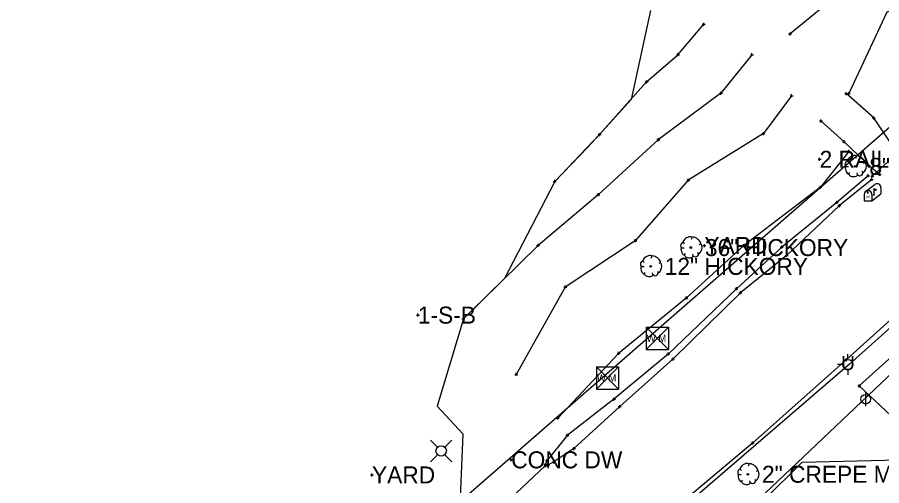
# Model space of a CAD drawing. Extents: x -1 to 1157254, y -1 to 2021979.
# Drawn here: x 1147084.1 to 1147450.2, y 2017275.4 to 2017473.9 of the extents above; entities that cross this region are included whole.
import ezdxf

# ---------------------------------------------------------------- set-up
doc = ezdxf.new("R2010")
doc.units = 0
for name, color, linetype in [('S_BUILDING_ANNOT', 7, 'Continuous'), ('S_CAL_CORNER_ANNOT', 7, 'Continuous'), ('S_CATCH_BASIN', 7, 'Continuous'), ('S_CONTOUR_ANNOT', 7, 'Continuous'), ('S_CONTOUR_MAJOR', 7, 'Continuous'), ('S_CROSS_DRAIN', 7, 'Continuous'), ('S_CTL_TABLE', 7, 'Continuous'), ('S_CURB', 7, 'Continuous'), ('S_DRIVEWAY_ANNOT', 7, 'Continuous'), ('S_DROP_INLET', 7, 'Continuous'), ('S_DROP_INLET_ANNOT', 7, 'Continuous'), ('S_EDGE_BITUMINOUS_ANNOT', 7, 'Continuous'), ('S_ENV_CONSTRAINT', 7, 'Continuous'), ('S_FENCE', 7, 'Continuous'), ('S_GAS_PUMP_ISLAND_ANNOT', 7, 'Continuous'), ('S_GATE', 7, 'Continuous'), ('S_GATE_ANNOT', 7, 'Continuous')]:
    doc.layers.add(name, color=color, linetype=linetype)

msp = doc.modelspace()

# ---------------------------------------------------------------- linework, layer by layer
at = {"layer": 'S_BUILDING_ANNOT'}
for p, q in [((1147435.23, 2017440.88), (1147435.23, 2017442.16)), ((1147434.6, 2017441.52), (1147435.87, 2017441.52)), ((1147435.23, 2017441.52), (1147435.23, 2017441.52)), ((1147446.26, 2017431.23), (1147447.53, 2017431.23)), ((1147446.89, 2017430.59), (1147446.89, 2017431.87)), ((1147446.89, 2017431.23), (1147446.89, 2017431.23)), ((1147423.84, 2017429.96), (1147425.11, 2017429.96)), ((1147424.48, 2017429.32), (1147424.48, 2017430.59)), ((1147424.48, 2017429.96), (1147424.48, 2017429.96)), ((1147433.64, 2017421.15), (1147434.91, 2017421.15)), ((1147434.28, 2017420.52), (1147434.28, 2017421.79)), ((1147434.28, 2017421.15), (1147434.28, 2017421.15)), ((1147423.31, 2017413.68), (1147424.58, 2017413.68)), ((1147423.94, 2017413.04), (1147423.94, 2017414.31)), ((1147423.94, 2017413.68), (1147423.94, 2017413.68)), ((1147443.32, 2017411.89), (1147443.31, 2017413.16)), ((1147442.68, 2017412.53), (1147443.95, 2017412.53)), ((1147443.31, 2017412.53), (1147443.31, 2017412.53)), ((1147443.85, 2017406.72), (1147445.12, 2017406.72)), ((1147444.49, 2017406.09), (1147444.49, 2017407.36)), ((1147444.49, 2017406.72), (1147444.49, 2017406.72)), ((1147445.58, 2017406.59), (1147446.86, 2017406.59)), ((1147446.02, 2017404.54), (1147446.01, 2017405.82)), ((1147446.22, 2017405.96), (1147446.22, 2017407.23)), ((1147446.22, 2017406.59), (1147446.22, 2017406.59)), ((1147448.78, 2017407.27), (1147450.06, 2017407.27)), ((1147449.42, 2017406.64), (1147449.42, 2017407.91)), ((1147449.42, 2017407.27), (1147449.42, 2017407.27)), ((1147445.38, 2017405.18), (1147446.65, 2017405.18)), ((1147446.01, 2017405.18), (1147446.01, 2017405.18)), ((1147430.58, 2017395.42), (1147431.85, 2017395.42)), ((1147431.22, 2017394.78), (1147431.22, 2017396.05)), ((1147431.22, 2017395.42), (1147431.22, 2017395.42)), ((1147432.34, 2017393.43), (1147432.34, 2017394.7)), ((1147431.7, 2017394.06), (1147432.98, 2017394.06)), ((1147432.34, 2017394.06), (1147432.34, 2017394.06)), ((1147374.5, 2017377.15), (1147375.77, 2017377.15)), ((1147375.13, 2017376.51), (1147375.13, 2017377.79)), ((1147375.13, 2017377.15), (1147375.13, 2017377.15)), ((1147407.28, 2017376.47), (1147408.56, 2017376.48)), ((1147407.92, 2017375.84), (1147407.92, 2017377.11)), ((1147407.92, 2017376.48), (1147407.92, 2017376.48)), ((1147409.34, 2017372.95), (1147410.61, 2017372.96)), ((1147409.97, 2017372.32), (1147409.97, 2017373.59)), ((1147409.97, 2017372.96), (1147409.97, 2017372.96)), ((1147388.04, 2017358.85), (1147389.31, 2017358.85)), ((1147388.68, 2017358.22), (1147388.67, 2017359.49)), ((1147388.68, 2017358.85), (1147388.68, 2017358.85)), ((1147390.38, 2017356.48), (1147390.38, 2017357.75)), ((1147389.74, 2017357.12), (1147391.02, 2017357.12)), ((1147390.38, 2017357.12), (1147390.38, 2017357.12)), ((1147253.16, 2017347.66), (1147254.43, 2017347.66)), ((1147253.8, 2017347.03), (1147253.79, 2017348.3)), ((1147253.79, 2017347.66), (1147253.79, 2017347.66)), ((1147359.14, 2017331.13), (1147360.41, 2017331.14)), ((1147359.78, 2017330.5), (1147359.78, 2017331.77)), ((1147359.78, 2017331.13), (1147359.78, 2017331.13)), ((1147361.23, 2017329.08), (1147362.51, 2017329.08)), ((1147361.87, 2017328.45), (1147361.87, 2017329.72)), ((1147361.87, 2017329.08), (1147361.87, 2017329.08)), ((1147434.65, 2017328.79), (1147435.92, 2017328.8)), ((1147435.29, 2017328.16), (1147435.28, 2017329.43)), ((1147435.29, 2017328.79), (1147435.29, 2017328.79)), ((1147336.21, 2017312.03), (1147337.48, 2017312.03)), ((1147336.84, 2017311.4), (1147336.84, 2017312.67)), ((1147336.84, 2017312.03), (1147336.84, 2017312.03)), ((1147338.65, 2017308.93), (1147339.92, 2017308.93)), ((1147339.29, 2017308.29), (1147339.28, 2017309.56)), ((1147339.28, 2017308.93), (1147339.28, 2017308.93)), ((1147316.4, 2017296.71), (1147317.68, 2017296.71)), ((1147317.04, 2017296.08), (1147317.04, 2017297.35)), ((1147317.04, 2017296.71), (1147317.04, 2017296.71)), ((1147394.89, 2017293.45), (1147396.16, 2017293.46)), ((1147395.53, 2017292.82), (1147395.53, 2017294.09)), ((1147395.53, 2017293.46), (1147395.53, 2017293.46)), ((1147319.27, 2017291.08), (1147320.54, 2017291.08)), ((1147319.91, 2017290.45), (1147319.9, 2017291.72)), ((1147319.91, 2017291.08), (1147319.91, 2017291.08)), ((1147292.68, 2017286.34), (1147293.95, 2017286.34)), ((1147293.32, 2017285.71), (1147293.32, 2017286.98)), ((1147293.32, 2017286.34), (1147293.32, 2017286.34)), ((1147307.78, 2017283.2), (1147307.77, 2017284.47)), ((1147307.82, 2017285.94), (1147309.09, 2017285.94)), ((1147307.84, 2017283.72), (1147307.84, 2017284.99)), ((1147308.46, 2017285.31), (1147308.46, 2017286.58)), ((1147308.46, 2017285.94), (1147308.46, 2017285.94)), ((1147308.89, 2017283.46), (1147308.89, 2017284.73)), ((1147310.74, 2017285.47), (1147312.01, 2017285.47)), ((1147311.38, 2017284.84), (1147311.38, 2017286.11)), ((1147311.38, 2017285.47), (1147311.38, 2017285.47)), ((1147307.14, 2017283.83), (1147308.41, 2017283.84)), ((1147307.2, 2017284.35), (1147308.47, 2017284.36)), ((1147307.77, 2017283.83), (1147307.77, 2017283.83)), ((1147307.84, 2017284.36), (1147307.84, 2017284.36)), ((1147308.26, 2017284.09), (1147309.53, 2017284.1)), ((1147308.89, 2017284.09), (1147308.89, 2017284.09)), ((1147233.73, 2017279.96), (1147235, 2017279.96)), ((1147234.36, 2017279.32), (1147234.36, 2017280.59)), ((1147234.36, 2017279.96), (1147234.36, 2017279.96))]:
    msp.add_line(p, q, dxfattribs=at)
at = {"layer": 'S_CAL_CORNER_ANNOT'}
msp.add_lwpolyline([(1148176.11, 2017926.04), (1148136.14, 2017895.28), (1148103.22, 2017868.95), (1148054.86, 2017832.59), (1147994.13, 2017784.96), (1147955.31, 2017755.81), (1147823.06, 2017654.27), (1147729.59, 2017581.35), (1147643.02, 2017515.61), (1147594.54, 2017475.05), (1147501.21, 2017388.35), (1147435.29, 2017328.79), (1147395.53, 2017293.46), (1147348.75, 2017254.13), (1147258.66, 2017171.57), (1147166.99, 2017089.79), (1147151.24, 2017076.13), (1147027.41, 2016982.56), (1146975.56, 2016939.41), (1146851.18, 2016835.15), (1146821.23, 2016867.05), (1146788.36, 2016903.2)], dxfattribs=at)
at = {"layer": 'S_CATCH_BASIN'}
for p, q in [((1147435.92, 2017328.87), (1147435.92, 2017331.11)), ((1147433.83, 2017326.74), (1147431.5, 2017326.74)), ((1147436, 2017322.32), (1147436, 2017324.64)), ((1147443.47, 2017309.11), (1147443.47, 2017314.89)), ((1147262.07, 2017291.69), (1147259.09, 2017294.67)), ((1147265.25, 2017291.69), (1147268.23, 2017294.67)), ((1147262.07, 2017288.51), (1147259.09, 2017285.53)), ((1147265.25, 2017288.51), (1147268.23, 2017285.53))]:
    msp.add_line(p, q, dxfattribs=at)
for centre, radius in [((1147435.92, 2017326.76), 2.13), ((1147443.47, 2017312.04), 2.05), ((1147263.67, 2017290.11), 2.21)]:
    msp.add_circle(centre, radius, dxfattribs=at)
at = {"layer": 'S_CONTOUR_ANNOT'}
for p, q in [((1147350.54, 2017342.55), (1147359.87, 2017342.55)), ((1147350.54, 2017342.55), (1147350.54, 2017333.06)), ((1147350.54, 2017342.55), (1147359.87, 2017333.06)), ((1147359.87, 2017342.55), (1147350.54, 2017333.06)), ((1147359.87, 2017342.55), (1147359.87, 2017333.06)), ((1147350.54, 2017333.06), (1147359.87, 2017333.06)), ((1147329.41, 2017325.78), (1147338.75, 2017325.78)), ((1147329.41, 2017325.78), (1147329.41, 2017316.29)), ((1147329.41, 2017325.78), (1147338.75, 2017316.29)), ((1147338.75, 2017325.78), (1147329.41, 2017316.29)), ((1147338.75, 2017325.78), (1147338.75, 2017316.29)), ((1147329.41, 2017316.29), (1147338.75, 2017316.29))]:
    msp.add_line(p, q, dxfattribs=at)
msp.add_lwpolyline([(1148171.01, 2018007.64), (1148133.82, 2017978.13), (1147884.86, 2017790.18), (1147810.34, 2017733.24), (1147725.21, 2017658.34), (1147638.36, 2017588.8), (1147507.67, 2017474.52), (1147125.41, 2017140.99), (1145970.62, 2016384.06)], dxfattribs=at)
at = {"layer": 'S_CROSS_DRAIN'}
for p, q in [((1147443.3, 2017400.07), (1147447.44, 2017403.17)), ((1147449.87, 2017401.7), (1147449.87, 2017398.99)), ((1147442.75, 2017398.79), (1147442.75, 2017396.08)), ((1147446.07, 2017396.08), (1147449.87, 2017398.99)), ((1147446.07, 2017398.79), (1147446.07, 2017396.08)), ((1147446.92, 2017401.35), (1147446.92, 2017398.64)), ((1147442.75, 2017396.08), (1147446.07, 2017396.08))]:
    msp.add_line(p, q, dxfattribs=at)
for points in [[(1147443.93, 2017399.91), (1147444.16, 2017399.77), (1147444.16, 2017399.38), (1147444.46, 2017399.38), (1147444.46, 2017399.74), (1147444.27, 2017399.99), (1147443.93, 2017399.94)], [(1147446.92, 2017401.35), (1147448.03, 2017400.69), (1147446.92, 2017400.34)]]:
    msp.add_lwpolyline(points, dxfattribs=at)
for centre, end in [((1147448.21, 2017401.7), 117.5718), ((1147444.41, 2017398.79), 180)]:
    msp.add_arc(centre, 1.66, 0, end, dxfattribs=at)
msp.add_ellipse((1147446.92, 2017398.64), major_axis=(0.145, 0.132), ratio=0.564646, dxfattribs=at)
at = {"layer": 'S_CTL_TABLE'}
for p, q in [((1147374.84, 2017470.31), (1147374.84, 2017471.58)), ((1147374.21, 2017470.94), (1147375.48, 2017470.94)), ((1147374.84, 2017470.94), (1147374.84, 2017470.94)), ((1147411.4, 2017466.2), (1147411.4, 2017467.47)), ((1147410.76, 2017466.84), (1147412.03, 2017466.84)), ((1147411.4, 2017466.84), (1147411.4, 2017466.84)), ((1147363.3, 2017458.01), (1147364.57, 2017458.01)), ((1147363.94, 2017457.38), (1147363.93, 2017458.65)), ((1147363.93, 2017458.01), (1147363.93, 2017458.01)), ((1147394.6, 2017458), (1147395.87, 2017458)), ((1147395.24, 2017457.37), (1147395.23, 2017458.64)), ((1147395.24, 2017458), (1147395.24, 2017458)), ((1147350.05, 2017446.47), (1147351.32, 2017446.48)), ((1147350.69, 2017445.84), (1147350.69, 2017447.11)), ((1147350.69, 2017446.47), (1147350.69, 2017446.47)), ((1147382.11, 2017441.06), (1147382.11, 2017442.33)), ((1147436.29, 2017440.87), (1147436.29, 2017442.14)), ((1147381.47, 2017441.69), (1147382.74, 2017441.7)), ((1147382.11, 2017441.69), (1147382.11, 2017441.69)), ((1147411.42, 2017440.58), (1147412.69, 2017440.59)), ((1147412.06, 2017439.95), (1147412.05, 2017441.22)), ((1147412.06, 2017440.59), (1147412.06, 2017440.59)), ((1147435.66, 2017441.5), (1147436.93, 2017441.5)), ((1147436.29, 2017441.5), (1147436.29, 2017441.5)), ((1147330.14, 2017424.17), (1147331.41, 2017424.17)), ((1147330.78, 2017423.53), (1147330.78, 2017424.81)), ((1147330.78, 2017424.17), (1147330.78, 2017424.17)), ((1147399.46, 2017424.58), (1147400.73, 2017424.58)), ((1147400.1, 2017423.95), (1147400.1, 2017425.22)), ((1147400.1, 2017424.58), (1147400.1, 2017424.58)), ((1147355, 2017422), (1147356.27, 2017422)), ((1147355.64, 2017421.36), (1147355.63, 2017422.64)), ((1147355.63, 2017422), (1147355.63, 2017422)), ((1147435.74, 2017417.04), (1147437.01, 2017417.05)), ((1147436.38, 2017416.41), (1147436.37, 2017417.68)), ((1147436.37, 2017417.05), (1147436.37, 2017417.05)), ((1147368.28, 2017404.2), (1147368.28, 2017405.47)), ((1147311.1, 2017404.32), (1147312.38, 2017404.32)), ((1147311.74, 2017403.69), (1147311.74, 2017404.96)), ((1147311.74, 2017404.32), (1147311.74, 2017404.32)), ((1147367.65, 2017404.83), (1147368.92, 2017404.83)), ((1147368.28, 2017404.83), (1147368.28, 2017404.83)), ((1147423.63, 2017401.87), (1147424.9, 2017401.88)), ((1147424.26, 2017401.24), (1147424.26, 2017402.51)), ((1147424.26, 2017401.87), (1147424.26, 2017401.87)), ((1147329.53, 2017398.69), (1147330.8, 2017398.69)), ((1147330.17, 2017398.05), (1147330.16, 2017399.32)), ((1147330.16, 2017398.69), (1147330.16, 2017398.69)), ((1147345.86, 2017378.51), (1147345.86, 2017379.79)), ((1147304.06, 2017377.22), (1147305.33, 2017377.22)), ((1147304.7, 2017376.58), (1147304.69, 2017377.86)), ((1147304.69, 2017377.22), (1147304.69, 2017377.22)), ((1147345.22, 2017379.15), (1147346.5, 2017379.15)), ((1147345.86, 2017379.15), (1147345.86, 2017379.15)), ((1147391.1, 2017377.06), (1147392.37, 2017377.06)), ((1147391.73, 2017376.43), (1147391.73, 2017377.7)), ((1147391.73, 2017377.06), (1147391.73, 2017377.06)), ((1147315.57, 2017359.53), (1147316.84, 2017359.53)), ((1147316.21, 2017358.89), (1147316.21, 2017360.16)), ((1147316.21, 2017359.53), (1147316.21, 2017359.53)), ((1147366.8, 2017354.89), (1147368.08, 2017354.89)), ((1147367.44, 2017354.25), (1147367.44, 2017355.53)), ((1147367.44, 2017354.89), (1147367.44, 2017354.89)), ((1147273.06, 2017345.39), (1147273.06, 2017346.66)), ((1147272.42, 2017346.02), (1147273.69, 2017346.03)), ((1147273.06, 2017346.02), (1147273.06, 2017346.02)), ((1147338.79, 2017330.79), (1147338.78, 2017332.07)), ((1147338.15, 2017331.43), (1147339.42, 2017331.43)), ((1147338.79, 2017331.43), (1147338.79, 2017331.43)), ((1147294.83, 2017322.55), (1147296.1, 2017322.55)), ((1147295.47, 2017321.92), (1147295.46, 2017323.19)), ((1147295.47, 2017322.55), (1147295.47, 2017322.55)), ((1147440.09, 2017317.65), (1147441.36, 2017317.65)), ((1147440.73, 2017317.02), (1147440.73, 2017318.29)), ((1147440.73, 2017317.65), (1147440.73, 2017317.65)), ((1147312.42, 2017304.05), (1147313.7, 2017304.05)), ((1147313.06, 2017303.41), (1147313.06, 2017304.69)), ((1147313.06, 2017304.05), (1147313.06, 2017304.05))]:
    msp.add_line(p, q, dxfattribs=at)
at = {"layer": 'S_CURB'}
for p, q in [((1147435.73, 2017412.92), (1147436.24, 2017412.34)), ((1147439.53, 2017414.94), (1147439.14, 2017414.08)), ((1147435.07, 2017410.6), (1147436.2, 2017410.6)), ((1147443.09, 2017412.15), (1147442.43, 2017411.88)), ((1147436.24, 2017407.42), (1147436.7, 2017408.12)), ((1147439.91, 2017407.15), (1147439.84, 2017407.93)), ((1147442.32, 2017408.04), (1147441.85, 2017408.47)), ((1147369.93, 2017380.53), (1147369.54, 2017379.68)), ((1147365.47, 2017376.2), (1147366.6, 2017376.2)), ((1147366.13, 2017378.52), (1147366.64, 2017377.94)), ((1147373.49, 2017377.75), (1147372.83, 2017377.47)), ((1147352.9, 2017372.58), (1147352.52, 2017371.72)), ((1147366.64, 2017373.02), (1147367.1, 2017373.72)), ((1147370.32, 2017372.75), (1147370.24, 2017373.52)), ((1147372.72, 2017373.64), (1147372.25, 2017374.07)), ((1147349.11, 2017370.56), (1147349.61, 2017369.98)), ((1147356.47, 2017369.79), (1147355.81, 2017369.52)), ((1147348.45, 2017368.24), (1147349.57, 2017368.24)), ((1147349.61, 2017365.06), (1147350.08, 2017365.76)), ((1147353.29, 2017364.79), (1147353.21, 2017365.56)), ((1147355.69, 2017365.68), (1147355.23, 2017366.11)), ((1147394.1, 2017284.48), (1147393.71, 2017283.62)), ((1147390.31, 2017282.46), (1147390.81, 2017281.88)), ((1147397.67, 2017281.69), (1147397.01, 2017281.42)), ((1147389.65, 2017280.14), (1147390.77, 2017280.14)), ((1147390.81, 2017276.96), (1147391.27, 2017277.66)), ((1147394.49, 2017276.69), (1147394.41, 2017277.47)), ((1147396.89, 2017277.58), (1147396.43, 2017278.01))]:
    msp.add_line(p, q, dxfattribs=at)
for centre in [(1147438.97, 2017410.69), (1147369.37, 2017376.29), (1147352.35, 2017368.33), (1147393.54, 2017280.23)]:
    msp.add_circle(centre, 0.34, dxfattribs=at)
for centre, major_axis, ratio, start_param, end_param in [((1147435.4, 2017411.78), (0.31, 1.03), 0.646762, 0, 3.141593), ((1147437.63, 2017413.89), (1.86, 1.08), 0.471018, 0, 3.141593), ((1147441.29, 2017413.57), (-1.81, 1.36), 0.405113, 3.141593, 6.283186), ((1147435.71, 2017409.13), (-0.61, 1.6), 0.420543, 6.283185, 9.424777), ((1147442.64, 2017410.16), (0.46, 2.04), 0.482994, 3.141593, 6.283185), ((1147438.17, 2017407.35), (-1.83, 0.19), 0.529943, 0, 3.141593), ((1147441.12, 2017407.64), (1.09, 0.46), 0.711534, 3.141592, 6.283185), ((1147368.04, 2017379.49), (1.86, 1.08), 0.471018, 0, 3.141593), ((1147371.69, 2017379.17), (-1.81, 1.36), 0.405113, 3.141593, 6.283186), ((1147365.8, 2017377.38), (0.31, 1.03), 0.646762, 0, 3.141593), ((1147366.11, 2017374.73), (-0.61, 1.6), 0.420543, 6.283185, 9.424777), ((1147373.04, 2017375.76), (0.46, 2.04), 0.482994, 3.141593, 6.283185), ((1147351.01, 2017371.53), (1.86, 1.08), 0.471018, 0, 3.141593), ((1147354.66, 2017371.21), (-1.81, 1.36), 0.405113, 3.141593, 6.283186), ((1147368.57, 2017372.95), (-1.83, 0.19), 0.529943, 0, 3.141593), ((1147371.52, 2017373.24), (1.09, 0.46), 0.711534, 3.141592, 6.283185), ((1147348.78, 2017369.42), (0.31, 1.03), 0.646762, 0, 3.141593), ((1147356.02, 2017367.8), (0.46, 2.04), 0.482994, 3.141593, 6.283185), ((1147349.08, 2017366.77), (-0.61, 1.6), 0.420543, 6.283185, 9.424777), ((1147351.54, 2017364.99), (-1.83, 0.19), 0.529943, 0, 3.141593), ((1147354.5, 2017365.28), (1.09, 0.46), 0.711534, 3.141592, 6.283185), ((1147392.21, 2017283.43), (1.86, 1.08), 0.471018, 0, 3.141593), ((1147395.86, 2017283.11), (-1.81, 1.36), 0.405113, 3.141593, 6.283186), ((1147389.97, 2017281.32), (0.31, 1.03), 0.646762, 0, 3.141593), ((1147397.22, 2017279.7), (0.46, 2.04), 0.482994, 3.141593, 6.283185), ((1147390.28, 2017278.67), (-0.61, 1.6), 0.420543, 6.283185, 9.424777), ((1147395.7, 2017277.18), (1.09, 0.46), 0.711534, 3.141592, 6.283185), ((1147392.74, 2017276.89), (-1.83, 0.19), 0.529943, 0, 3.141593)]:
    msp.add_ellipse(centre, major_axis=major_axis, ratio=ratio, start_param=start_param, end_param=end_param, dxfattribs=at)
at = {"layer": 'S_DRIVEWAY_ANNOT'}
for points in [[(1147444.49, 2017406.72), (1147431.22, 2017395.42), (1147407.92, 2017376.48), (1147388.68, 2017358.85), (1147359.78, 2017331.13), (1147336.84, 2017312.03), (1147317.04, 2017296.71), (1147308.46, 2017285.94), (1147307.84, 2017284.36)], [(1147446.01, 2017405.18), (1147432.34, 2017394.06), (1147409.97, 2017372.96), (1147390.38, 2017357.12), (1147361.87, 2017329.08), (1147339.28, 2017308.93), (1147319.91, 2017291.08), (1147311.38, 2017285.47), (1147308.89, 2017284.09)]]:
    msp.add_lwpolyline(points, dxfattribs=at)
at = {"layer": 'S_DROP_INLET'}
msp.add_lwpolyline([(1148195.53, 2017935.77), (1148138.82, 2017892.99), (1148034.43, 2017809.59), (1147909.47, 2017714.32), (1147828.88, 2017654.71), (1147681.29, 2017538.62), (1147545.03, 2017424.01), (1147436.65, 2017326.84), (1147356.29, 2017257.74), (1147237.67, 2017148.84), (1147152.37, 2017082.27), (1147079.41, 2017020.24), (1146950.46, 2016911.58), (1146849.38, 2016826.65), (1146763.18, 2016745.2), (1146663.11, 2016665.75), (1146626.02, 2016634.68), (1146520.54, 2016557.46), (1146484.38, 2016531.03)], dxfattribs=at)
at = {"layer": 'S_DROP_INLET_ANNOT'}
for points in [[(1147460.88, 2017419.94), (1147446.22, 2017406.59)], [(1147307.77, 2017283.83), (1147293.03, 2017269.94)]]:
    msp.add_lwpolyline(points, dxfattribs=at)
at = {"layer": 'S_EDGE_BITUMINOUS_ANNOT'}
for points in [[(1147558.92, 2017595.76), (1147530.93, 2017571.5), (1147508.22, 2017548.29), (1147481.26, 2017527.48), (1147462.7, 2017506.77), (1147439.97, 2017490.32), (1147411.4, 2017466.84)], [(1147577.73, 2017571.25), (1147545.61, 2017553.62), (1147527.81, 2017524.72), (1147497.72, 2017507.91), (1147483.68, 2017485.4), (1147452.43, 2017476.09), (1147436.29, 2017441.5)], [(1147311.74, 2017404.32), (1147330.78, 2017424.17), (1147350.69, 2017446.47), (1147363.93, 2017458.01), (1147374.84, 2017470.94)], [(1147395.24, 2017458), (1147382.11, 2017441.69), (1147355.63, 2017422), (1147330.16, 2017398.69), (1147304.69, 2017377.22), (1147273.06, 2017346.02)], [(1147412.06, 2017440.59), (1147400.1, 2017424.58), (1147368.28, 2017404.83), (1147345.86, 2017379.15), (1147316.21, 2017359.53), (1147295.47, 2017322.55)], [(1147436.37, 2017417.05), (1147424.26, 2017401.87), (1147391.73, 2017377.06), (1147367.44, 2017354.89), (1147338.79, 2017331.43), (1147313.06, 2017304.05)], [(1147469.11, 2017343.88), (1147457.58, 2017332.94), (1147440.73, 2017317.65), (1147454.3, 2017305.05), (1147467.17, 2017317.45), (1147481.1, 2017327.42), (1147497.6, 2017311.18), (1147487.31, 2017298.3), (1147470.6, 2017284.1)]]:
    msp.add_lwpolyline(points, dxfattribs=at)
at = {"layer": 'S_ENV_CONSTRAINT'}
for points in [[(1147459.07, 2017415.86), (1147454.12, 2017420.51), (1147446.89, 2017431.23), (1147435.23, 2017441.52)], [(1147424.48, 2017429.96), (1147434.28, 2017421.15), (1147443.31, 2017412.53), (1147449.42, 2017407.27)]]:
    msp.add_lwpolyline(points, dxfattribs=at)
at = {"layer": 'S_FENCE'}
msp.add_lwpolyline([(1148182.05, 2017918.06), (1148146.03, 2017882.74), (1148036.88, 2017800.65), (1147915.13, 2017710.9), (1147841.97, 2017653.39), (1147689.75, 2017529.1), (1147550.85, 2017419.33), (1147452.64, 2017321.35), (1147370.71, 2017243.52), (1147258.33, 2017138.3), (1147166.15, 2017078.02), (1147070.18, 2016992.83), (1146962.81, 2016905.87), (1146854.86, 2016827.91), (1146747.33, 2016742.81), (1146665.82, 2016680.99), (1146623.06, 2016638.6), (1146514.26, 2016556.71), (1146391.39, 2016471.4), (1146322.08, 2016427.51), (1146235.84, 2016374), (1146176.66, 2016335.01), (1146181.42, 2016326.5)], dxfattribs=at)
at = {"layer": 'S_GAS_PUMP_ISLAND_ANNOT'}
for points in [[(1147352.3, 2017476.79), (1147344.1, 2017439.09), (1147337.44, 2017431.63), (1147330.78, 2017424.17), (1147325.58, 2017418.75), (1147318.66, 2017411.53), (1147311.74, 2017404.32), (1147290.46, 2017363.18), (1147283.34, 2017356.16), (1147276.22, 2017349.14), (1147273.06, 2017346.02), (1147262, 2017309.15), (1147272.85, 2017297.31), (1147271, 2017253.12)], [(1147400.12, 2017269.13), (1147416.61, 2017285.39), (1147463.11, 2017286.45)]]:
    msp.add_lwpolyline(points, dxfattribs=at)

# ---------------------------------------------------------------- texts
at = {"layer": 'S_CONTOUR_ANNOT'}
for p in [(1147350.74, 2017336.32), (1147329.62, 2017319.55)]:
    msp.add_text('W M', height=2.999, dxfattribs=at).set_placement(p)
at = {"layer": 'S_CONTOUR_MAJOR'}
msp.add_text('U', height=6, dxfattribs=at).set_placement((1147433.02, 2017324.29))
at = {"layer": 'S_CROSS_DRAIN'}
msp.add_text('US', height=0.96, dxfattribs=at).set_placement((1147443.51, 2017397.27))
at = {"layer": 'S_GATE'}
for s, p in [('2 RAIL WD FE', (1147423.94, 2017410.08)), ('YARD', (1147375.13, 2017373.55)), ('1-S-B', (1147253.79, 2017344.06)), ('CONC DW', (1147293.32, 2017282.74)), ('YARD', (1147234.36, 2017276.36))]:
    msp.add_text(s, height=7.2, dxfattribs=at).set_placement(p)
at = {"layer": 'S_GATE_ANNOT'}
for s, p in [('8" CREPE MYRTLE', (1147444.97, 2017407.09)), ('36" HICKORY', (1147375.37, 2017372.69)), ('12" HICKORY', (1147358.35, 2017364.73)), ('2" CREPE MYRTLE', (1147399.54, 2017276.63))]:
    msp.add_text(s, height=7.2, dxfattribs=at).set_placement(p)

doc.saveas('drawing.dxf')
